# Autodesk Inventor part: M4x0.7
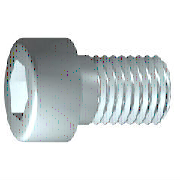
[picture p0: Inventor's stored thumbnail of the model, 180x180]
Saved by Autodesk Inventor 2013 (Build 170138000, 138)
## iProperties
IsCustomPart: 1
Created: 2009-02
Part Number: M4x0.7
Material: 강, 연강
Description: 6각머리 태핑 나사
Document SubType Name: Modeling
Standard: KS B 1003
Designer: SeoGD™[esajin.kr]
Standards Organization: KS
Language: ko-KR
Size Designation: M 4 x 16
Categories: <MemberInstance><Categories><Category DisplayName="조임쇠" InternalName="e4da775c-781d-43d5-af7c-5136215cf5a6" Mnemonic="FSTN"><Category DisplayName="볼트" InternalN
Density: 7.86 g/cm^3
Mass: 2.62973 g
Surface Area: 3.81118 cm^2
Volume: 0.334572 cm^3
Author: SeoGD™[esajin.kr]
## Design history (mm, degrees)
sketch "스케치1"
  geometry: L1 (-1, 0)-(16, 0); L2 (16, 0)-(16, 2); L3 (16, 2)-(1.75, 2); L4 (1.75, 2)-(1.32, 2); L5 (1.32, 2)-(0, 2); L6 (0, 2)-(0, 3.5); L7 (0, 3.5)-(-4, 3.5); L8 (-4, 3.5)-(-4, 1.732); L9 (-4, 1.732)-(-2, 1.732); L10 (-2, 1.732)-(-1, 0); L11 (-8, 0)-(20, 0) reference; L12 (0, -0.7)-(0, 4.2) reference; L13 (1.75, 2)-(0, 2)
  constraints: 22 end point, 6 parallel, 2 collinear, 2 perpendicular, 1 horizontal, 1 point on line
  dimensions: "d1" = 14.25 distance from line of L3.end L2 (= GEL); "d2" = 0.42952 distance of L4.end L3.end (computed from GAL); "d3" = 4 distance between parallel lines of L8 L6 (= KOH); "d4" = 2 distance of L8.end L9.end (= INTI); "d5" = 60 deg angle of L10 L1; "d6" = 4 diameter of L3 L1 (= GD); "d7" = 4 diameter of L5 L1 (= BDM); "d8" = 3.4641 diameter of L9 L1 (= 1.1547 x SW); "d9" = 7 diameter of L7 L1 (= KOD); "d26" = 16 distance between parallel lines of L12 L2 (= NLG)
revolve "본체" sketch "스케치1" stored, may be unused: angle "d10" = 90 deg
sketch "스케치2"
  geometry: L1 (0, -4.9)-(0, 4.9) reference; L2 (-4.9, 0)-(4.9, 0) reference; L3 (1.732, 0)-(0.866, -1.5); L4 (0.866, -1.5)-(-0.866, -1.5); L5 (-0.866, -1.5)-(-1.732, 0); L6 (-1.732, 0)-(-0.866, 1.5); L7 (-0.866, 1.5)-(0.866, 1.5); L8 (0.866, 1.5)-(1.732, 0); 2 further points
  constraints: 12 end point, 1 coincident, 1 horizontal alignment, 1 point on line, 12 other
extrude "슬롯" join sketch "스케치2" stored distance "d11" = 10; taper "d12" = 0 deg
workplane "Work Plane1"
fillet "Fillet2" dims "d30" = 0.1 (= R)
body "Solid1"
fillet "모깎기1" dims "d17" = 0.4 (= RR)
feature "스레드" dims "d13" = 14.25 (= GEL), "d14" = 0
chamfer "모따기1" distance "d15" = 0.42941 (= -0.5 x SPD + 0.5 x GD); stored, may be unused: second distance "d16" = 0.42941 (= GUL), angle "d27" = 45 deg
other parameters: "GD" = 4 (= NND) [user parameter; used in 2 equation terms], "NLG" = 16 [user parameter; used in 1 equation term], "GEL" = 14.25 [user parameter; used in 2 equation terms], "KOD" = 7 [user parameter; used in 1 equation term], "KOH" = 4 [user parameter; used in 1 equation term], "INTI" = 2 [user parameter; used in 1 equation term], "GAL" = 0.42941 (= 0.61345 x PTC) [user parameter; used in 1 equation term], "GUL" = 0.42941 (= 0.61345 x PTC) [user parameter; used in 1 equation term], "BDM" = 4 (= NND) [user parameter; used in 1 equation term], "SW" = 3 [user parameter; used in 2 equation terms], "RR" = 0.4 [user parameter; used in 1 equation term], "SPD" = 3.14117 (= NND - 1.2269 x PTC) [user parameter; used in 1 equation term], "d19" = 0, "d28" = 0, "d29" = 0, "R" = 0.1 [user parameter; used in 1 equation term], "PHH" = 0.2 [user parameter], "GD1" = 3.14117 (= THREADDIA - 1.2269 x PTC) [user parameter], "THREADDIA" = 4 [user parameter; used in 1 equation term], "FAWI" = 45 deg [user parameter], "TPU" = 14.28571 (computed from PTC) [user parameter], "PTC" = 0.7 [user parameter; used in 5 equation terms], "NND" = 4 [user parameter; used in 3 equation terms], "TOA" = 30 deg [user parameter], "E0" = 3.465 (= 1.155 x SW) [user parameter]
